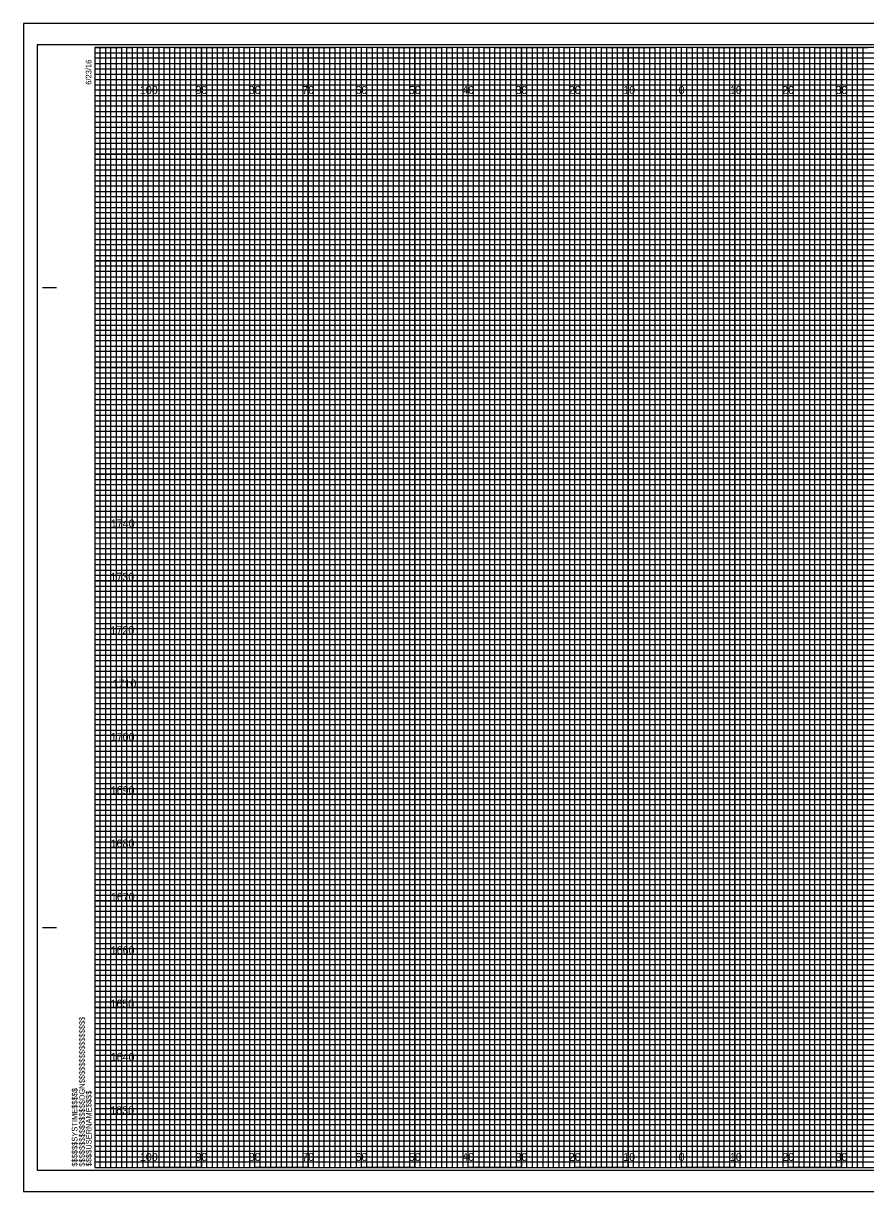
# Model space of a CAD drawing. Extents: x -13 to 323, y -5 to 6154.
# Drawn here: x -13.4 to 144.5, y 1755.5 to 1974.5 of the extents above; entities that cross this region are included whole.
import ezdxf

# ---------------------------------------------------------------- set-up
doc = ezdxf.new("R2010")
doc.units = 0
for name, color, linetype in [('Prop Retaining Wall', 7, 'Continuous'), ('Prop XS Alignment Label', 7, 'Continuous'), ('Prop XS DDE', 7, 'Continuous'), ('Prop XS DDE Elevations', 7, 'Continuous'), ('Prop XS DDE Slope Text', 7, 'Continuous'), ('Prop XS Earthwork Shape', 7, 'Continuous'), ('Prop XS Elevation Labels', 7, 'Continuous'), ('Prop XS Station Labels', 7, 'Continuous'), ('Raster_Level_0', 7, 'Continuous'), ('Scratch_Level_3', 7, 'Continuous'), ('Sheet Cutting Line CELL', 7, 'Continuous')]:
    doc.layers.add(name, color=color, linetype=linetype)

msp = doc.modelspace()

# ---------------------------------------------------------------- linework, layer by layer
at = {"layer": 'Prop Retaining Wall'}
for p, q in [((0, 1969), (260, 1969)), ((260, 1967.98), (0, 1967.98)), ((0, 1967.98), (0, 1967)), ((0, 1967), (260, 1967)), ((260, 1965.89), (0, 1965.89)), ((0, 1965.89), (0, 1964)), ((0, 1964), (320, 1964))]:
    msp.add_line(p, q, dxfattribs=at)
for points in [[(0, 1963), (270, 1963), (320, 1963), (320, 1962), (0, 1962)], [(0, 1961), (320, 1961), (320, 1959), (0, 1959)], [(0, 1958), (320, 1958), (320, 1957), (0, 1956.98)], [(0, 1956), (320, 1956), (320, 1954), (0, 1954)], [(0, 1953), (320, 1953), (320, 1952), (0, 1952)], [(0, 1951), (320, 1951), (320, 1949), (0, 1949)], [(0, 1948), (320, 1948), (320, 1947), (0, 1947)], [(0, 1946), (320, 1946), (320, 1944), (0, 1944)], [(0, 1943), (320, 1943), (320, 1942), (0, 1942)], [(0, 1941), (320, 1941), (320, 1939), (0, 1939)], [(0, 1938), (320, 1938), (320, 1937), (0, 1937)], [(0, 1936), (320, 1936), (320, 1933.95), (320, 1933), (320, 1932), (0, 1932)], [(0, 1934), (320, 1934), (320, 1933), (0, 1933)], [(0, 1931), (320, 1931), (320, 1929), (0, 1929.03)], [(0, 1929.03), (320, 1929), (320, 1928), (0, 1928)], [(0, 1927), (320, 1927), (320, 1926), (0, 1926)], [(0, 1924), (320, 1924), (320, 1923), (0, 1923)], [(0, 1922), (320, 1922), (320, 1921), (0, 1921)], [(-0.07, 1918.89), (320, 1918.89), (320, 1917.88), (-0.07, 1917.88)], [(0, 1917), (320, 1917), (320, 1916), (0, 1916)], [(0, 1914), (320, 1914), (320, 1913), (0, 1913)], [(0, 1912), (320, 1912), (320, 1911), (0, 1911)], [(0, 1909), (320, 1909), (320, 1908), (0, 1908)], [(0, 1907), (320, 1907), (320, 1906), (0, 1906)], [(0, 1904), (320, 1904), (320, 1903), (0, 1903)], [(0, 1902), (320, 1902), (320, 1901), (0, 1901)], [(0, 1899), (320, 1899), (319.99, 1897.98), (0, 1898)], [(0, 1897), (320, 1897), (320, 1896), (0, 1896)], [(0, 1894), (320, 1894), (320, 1893), (0, 1893)], [(0, 1892), (320, 1892), (320, 1891), (0, 1891)], [(0, 1889), (320, 1889), (320, 1888), (0, 1888)], [(0, 1887), (320, 1887), (320, 1886), (0, 1886)], [(0, 1884), (320, 1884), (320, 1883), (0, 1883)], [(0, 1882), (320, 1882), (320, 1881), (0, 1881)], [(0, 1879), (320, 1879), (320, 1878), (0, 1878)], [(0, 1876.99), (320.07, 1876.91), (320, 1876), (0, 1876)], [(0, 1874), (320, 1874), (320, 1873), (0, 1873)], [(0, 1872), (320, 1872), (320, 1871), (0, 1871)], [(0, 1869), (320, 1869), (320, 1868), (0, 1868)], [(0, 1867), (320, 1867), (320, 1866), (0, 1866)], [(0, 1864), (320, 1864), (320, 1863), (0, 1863)], [(0, 1862), (320, 1862), (320, 1861), (0, 1861)], [(0, 1859), (320, 1859), (320, 1858), (0, 1858)], [(0, 1857), (320, 1857), (320, 1856), (0, 1856)], [(0, 1854), (320, 1854), (320, 1853), (0, 1853)], [(0, 1852), (320, 1852), (320, 1851), (0, 1851)], [(0, 1849), (320, 1849), (320, 1848), (0, 1848)], [(0, 1847), (320, 1847), (320, 1846), (0, 1846)], [(0, 1844), (320, 1844), (320, 1843), (0, 1843)], [(0, 1842), (320, 1842), (320, 1841), (0, 1841)], [(0, 1839), (320, 1839), (319.99, 1837.98), (0, 1838)], [(0, 1837), (320, 1837), (320, 1836), (0, 1836)], [(0, 1834), (320, 1834), (320, 1833), (0, 1833)], [(0, 1832), (320, 1832), (320, 1831), (0, 1831)], [(0, 1829), (320, 1829), (320, 1828), (0, 1828)], [(0, 1827), (320, 1827), (320, 1826), (0, 1826)], [(0, 1824), (320, 1824), (320, 1823), (0, 1823)], [(0, 1822), (320, 1822), (320, 1821), (0, 1821)], [(0, 1819), (320, 1819), (320, 1818), (0, 1818)], [(0, 1816.99), (320.07, 1816.91), (320, 1816), (0, 1816)], [(0, 1814), (320, 1814), (320, 1813), (0, 1813)], [(0, 1812), (320, 1812), (320, 1811), (0, 1811)], [(0, 1809), (320, 1809), (320, 1808), (0, 1808)], [(0, 1807), (320, 1807), (320, 1806), (0, 1806)], [(0, 1804), (320, 1804), (320, 1803), (0, 1803)], [(0, 1802), (320, 1802), (320, 1801), (0, 1801)], [(0, 1799), (320, 1799), (320, 1798), (0, 1798)], [(0, 1797), (320, 1797), (320, 1796), (0, 1796)], [(0, 1794), (320, 1794), (320, 1793), (0, 1793)], [(0, 1792), (320, 1792), (320, 1791), (0, 1791)], [(0, 1789), (320, 1789), (320, 1788), (0, 1788)], [(0, 1787), (320, 1787), (320, 1786), (0, 1786)], [(0, 1784), (320, 1784), (320, 1783), (0, 1783)], [(0, 1782), (320, 1782), (320, 1781), (0, 1781)], [(0, 1779), (320, 1779), (320, 1778), (0, 1778)], [(0, 1777), (320, 1777), (320, 1776), (0, 1776)], [(0, 1774), (320, 1774), (320, 1773), (0, 1773)], [(0, 1772), (320, 1772), (320, 1771), (0, 1771)], [(0, 1769), (320, 1769), (320, 1768), (0, 1768)], [(0, 1767), (320, 1767), (320, 1766), (0, 1766)], [(0, 1764), (320, 1764), (320, 1763), (0, 1763)], [(0, 1762), (320, 1762), (320, 1761), (0, 1761)]]:
    msp.add_lwpolyline(points, dxfattribs=at)
at = {"layer": 'Prop XS Alignment Label'}
for p, q in [((-9.8, 1925), (-7.3, 1925)), ((-9.7, 1925), (-7.2, 1925)), ((-9.8, 1805), (-7.3, 1805)), ((-9.7, 1805), (-7.2, 1805)), ((0, 1760), (0, 1760)), ((0, 1760), (0, 1760)), ((0, 1760), (0, 1760)), ((0, 1760), (0, 1760)), ((0, 1760), (0, 1760)), ((0, 1760), (0, 1760)), ((0, 1760), (0, 1760))]:
    msp.add_line(p, q, dxfattribs=at)
msp.add_lwpolyline([(320, 1970), (0, 1970), (0, 1760), (320, 1760)], close=True, dxfattribs=at)
at = {"layer": 'Prop XS DDE'}
msp.add_lwpolyline([(-13.4, 1755.5), (323.3, 1755.5), (323.3, 1974.5), (-13.4, 1974.5)], close=True, dxfattribs=at)
at = {"layer": 'Prop XS DDE Elevations'}
for p, q in [((10, 1760), (10, 1970)), ((20, 1760), (20, 1970)), ((30, 1760), (30, 1970)), ((40, 1760), (40, 1970)), ((50, 1760), (50, 1970)), ((60, 1760), (60, 1970)), ((70, 1760), (70, 1970)), ((80, 1760), (80, 1970)), ((90, 1760), (90, 1970)), ((100, 1760), (100, 1970)), ((110, 1760), (110, 1970)), ((120, 1760), (120, 1970)), ((130, 1760), (130, 1970)), ((140, 1760), (140, 1970)), ((0, 1960), (320, 1960)), ((0, 1950), (320, 1950)), ((0, 1940), (320, 1940)), ((0, 1930), (320, 1930)), ((0, 1920), (320, 1920)), ((0, 1910), (320, 1910)), ((0, 1900), (320, 1900)), ((0, 1890), (320, 1890)), ((0, 1880), (320, 1880)), ((0, 1870), (320, 1870)), ((0, 1860), (320, 1860)), ((0, 1850), (320, 1850)), ((0, 1840), (320, 1840)), ((0, 1830), (320, 1830)), ((0, 1820), (320, 1820)), ((0, 1810), (320, 1810)), ((0, 1800), (320, 1800)), ((0, 1790), (320, 1790)), ((0, 1780), (320, 1780)), ((0, 1770), (320, 1770))]:
    msp.add_line(p, q, dxfattribs=at)
at = {"layer": 'Prop XS DDE Slope Text'}
msp.add_lwpolyline([(-10.8, 1759.5), (322.4, 1759.5), (322.4, 1970.5), (-10.8, 1970.5)], close=True, dxfattribs=at)
at = {"layer": 'Prop XS Earthwork Shape'}
for p, q in [((10, 1970), (0, 1970)), ((10, 1760), (10, 1970)), ((30, 1970), (20, 1970)), ((20, 1970), (20, 1760)), ((30, 1760), (30, 1970)), ((50, 1970), (40, 1970)), ((40, 1970), (40, 1760)), ((50, 1760), (50, 1970)), ((70, 1970), (60, 1970)), ((60, 1970), (60, 1760)), ((70, 1760), (70, 1970)), ((90, 1970), (80, 1970)), ((80, 1970), (80, 1760)), ((90, 1760), (90, 1970)), ((110, 1970), (100, 1970)), ((100, 1970), (100, 1760)), ((110, 1760), (110, 1970)), ((130, 1970), (120, 1970)), ((120, 1970), (120, 1760)), ((130, 1760), (130, 1970)), ((150, 1970), (140, 1970)), ((140, 1970), (140, 1760)), ((20, 1760), (10, 1760)), ((40, 1760), (30, 1760)), ((60, 1760), (50, 1760)), ((80, 1760), (70, 1760)), ((100, 1760), (90, 1760)), ((120, 1760), (110, 1760)), ((140, 1760), (130, 1760))]:
    msp.add_line(p, q, dxfattribs=at)
for points in [[(0, 1960), (320, 1960), (320, 1950), (0, 1950)], [(0, 1940), (320, 1940), (320, 1930), (0, 1930)], [(0, 1920), (320, 1920), (320, 1910), (0, 1910)], [(0, 1900), (320, 1900), (320, 1890), (0, 1890)], [(0, 1880), (320, 1880), (320, 1870), (0, 1870)], [(0, 1860), (320, 1860), (320, 1850), (0, 1850)], [(0, 1840), (320, 1840), (320, 1830), (0, 1830)], [(0, 1820), (320, 1820), (320, 1810), (0, 1810)], [(0, 1800), (320, 1800), (320, 1790), (0, 1790)], [(0, 1780), (320, 1780), (320, 1770), (0, 1770)]]:
    msp.add_lwpolyline(points, dxfattribs=at)
at = {"layer": 'Prop XS Elevation Labels'}
for points in [[(0, 1760), (1, 1760), (1, 1970), (2, 1970), (2, 1760)], [(2, 1760), (3, 1760), (3, 1970), (4, 1970), (4, 1760)], [(5, 1760), (6, 1760), (6, 1970), (7, 1970), (7, 1760)], [(7, 1760), (8, 1760), (8, 1970), (9, 1970), (9, 1760)], [(10, 1760), (11, 1760), (11, 1970), (12, 1970), (12, 1760)], [(12, 1760), (13, 1760), (13, 1970), (14, 1970), (14, 1760)], [(15, 1760), (16, 1760), (16, 1970), (17, 1970), (17, 1760)], [(17, 1760), (18, 1760), (18, 1970), (19, 1970), (19, 1760)], [(20, 1760), (21, 1760), (21, 1970), (22, 1970), (22, 1760)], [(22, 1760), (23, 1760), (23, 1970), (24, 1970), (24, 1760)], [(25, 1760), (26, 1760), (26, 1970), (27, 1970), (27, 1760)], [(27, 1760), (28, 1760), (28, 1970), (29, 1970), (29, 1760)], [(30, 1760), (31, 1760), (31, 1970), (32, 1970), (32, 1760)], [(32, 1760), (33, 1760), (33, 1970), (34, 1970), (34, 1760)], [(35, 1760), (36, 1760), (36, 1970), (37, 1970), (37, 1760)], [(37, 1760), (38, 1760), (38, 1970), (39, 1970), (39, 1760)], [(40, 1760), (41, 1760), (41, 1970), (42, 1970), (42, 1760)], [(42, 1760), (43, 1760), (43, 1970), (44, 1970), (44, 1760)], [(45, 1760), (46, 1760), (46, 1970), (47, 1970), (47, 1760)], [(47, 1760), (48, 1760), (48, 1970), (49, 1970), (49, 1760)], [(50, 1760), (51, 1760), (51, 1970), (52, 1970), (52, 1760)], [(52, 1760), (53, 1760), (53, 1970), (54, 1970), (54, 1760)], [(55, 1760), (56, 1760), (56, 1970), (57, 1970), (57, 1760)], [(57, 1760), (58, 1760), (58, 1970), (59, 1970), (59, 1760)], [(60, 1760), (61, 1760), (61, 1970), (62, 1970), (62, 1760)], [(62, 1760), (63, 1760), (63, 1970), (64, 1970), (64, 1760)], [(65, 1760), (66, 1760), (66, 1970), (67, 1970), (67, 1760)], [(67, 1760), (68, 1760), (68, 1970), (69, 1970), (69, 1760)], [(70, 1760), (71, 1760), (71, 1970), (72, 1970), (72, 1760)], [(72, 1760), (73, 1760), (73, 1970), (74, 1970), (74, 1760)], [(75, 1760), (76, 1760), (76, 1970), (77, 1970), (77, 1760)], [(77, 1760), (78, 1760), (78, 1970), (79, 1970), (79, 1760)], [(80, 1760), (81, 1760), (81, 1970), (82, 1970), (82, 1760)], [(82, 1760), (83, 1760), (83, 1970), (84, 1970), (84, 1760)], [(85, 1760), (86, 1760), (86, 1970), (87, 1970), (87, 1760)], [(87, 1760), (88, 1760), (88, 1970), (89, 1970), (89, 1760)], [(90, 1760), (91, 1760), (91, 1970), (92, 1970), (92, 1760)], [(92, 1760), (93, 1760), (93, 1970), (94, 1970), (94, 1760)], [(95, 1760), (96, 1760), (96, 1970), (97, 1970), (97, 1760)], [(97, 1760), (98, 1760), (98, 1970), (99, 1970), (99, 1760)], [(100, 1760), (101, 1760), (101, 1970), (102, 1970), (102, 1760)], [(102, 1760), (103, 1760), (103, 1970), (104, 1970), (104, 1760)], [(105, 1760), (106, 1760), (106, 1970), (107, 1970), (107, 1760)], [(107, 1760), (108, 1760), (108, 1970), (109, 1970), (109, 1760)], [(110, 1760), (111, 1760), (111, 1970), (112, 1970), (112, 1760)], [(112, 1760), (113, 1760), (113, 1970), (114, 1970), (114, 1760)], [(115, 1760), (116, 1760), (116, 1970), (117, 1970), (117, 1760)], [(117, 1760), (118, 1760), (118, 1970), (119, 1970), (119, 1760)], [(120, 1760), (121, 1760), (121, 1970), (122, 1970), (122, 1760)], [(122, 1760), (123, 1760), (123, 1970), (124, 1970), (124, 1760)], [(125, 1760), (126, 1760), (126, 1970), (127, 1970), (127, 1760)], [(127, 1760), (128, 1760), (128, 1970), (129, 1970), (129, 1760)], [(130, 1760), (131, 1760), (131, 1970), (132, 1970), (132, 1760)], [(132, 1760), (133, 1760), (133, 1970), (134, 1970), (134, 1760)], [(135, 1760), (136, 1760), (136, 1970), (137, 1970), (137, 1760)], [(137, 1760), (138, 1760), (138, 1970), (139, 1970), (139, 1760)], [(140, 1760), (141, 1760), (141, 1970), (142, 1970), (142, 1760)], [(142, 1760), (143, 1760), (143, 1970), (144, 1970), (144, 1760)]]:
    msp.add_lwpolyline(points, dxfattribs=at)
at = {"layer": 'Prop XS Station Labels'}
for points in [[(0, 1970), (5, 1970), (5, 1760), (15, 1760), (15, 1970), (25, 1970), (25, 1760), (35, 1760), (35, 1970), (45, 1970), (45, 1760), (55, 1760), (55, 1970), (65, 1970), (65, 1760), (75, 1760), (75, 1970), (85, 1970), (85, 1760), (95, 1760), (95, 1970), (105, 1970), (105, 1760), (115, 1760), (115, 1970), (125, 1970), (125, 1760), (135, 1760), (135, 1970), (145, 1970)], [(0, 1965), (275, 1965)], [(0, 1945), (320, 1945), (320, 1955), (0, 1955)], [(0, 1925), (320, 1925), (320, 1935), (0, 1935)], [(0, 1905), (320, 1905), (320, 1915), (0, 1915)], [(0, 1885), (320, 1885), (320, 1895), (0, 1895)], [(0, 1865), (320, 1865), (320, 1875), (0, 1875)], [(0, 1845), (320, 1845), (320, 1855), (0, 1855)], [(0, 1825), (320, 1825), (320, 1835), (0, 1835)], [(0, 1805), (320, 1805), (320, 1815), (0, 1815)], [(0, 1785), (320, 1785), (320, 1795), (0, 1795)], [(0, 1765), (320, 1765), (320, 1775), (0, 1775)]]:
    msp.add_lwpolyline(points, dxfattribs=at)
at = {"layer": 'Sheet Cutting Line CELL'}
for p, q in [((323.3, 1974.5), (-13.4, 1974.5)), ((-13.4, 1974.5), (-13.4, 1755.5)), ((-13.4, 1755.5), (323.3, 1755.5))]:
    msp.add_line(p, q, dxfattribs=at)

# ---------------------------------------------------------------- texts
at = {"layer": 'Prop XS Alignment Label'}
for s, p in [('6/23/16', (-0.65, 1963)), ('$$$$$$$$$$$$$$$$DGN$$$$$$$$$$$$$$$$', (-1.88, 1760.18)), ('$$$$$$SYSTIME$$$$$', (-3.26, 1760.18)), ('$$$$USERNAME$$$$', (-0.62, 1760.23))]:
    msp.add_text(s, height=1.05, rotation=90, dxfattribs=at).set_placement(p)
at = {"layer": 'Raster_Level_0'}
for s, p in [('100', (8.44, 1961.25)), ('90', (18.86, 1961.25)), ('80', (28.86, 1961.25)), ('70', (38.86, 1961.25)), ('60', (48.86, 1961.25)), ('50', (58.86, 1961.25)), ('40', (68.86, 1961.25)), ('30', (78.86, 1961.25)), ('20', (88.86, 1961.25)), ('10', (99.04, 1961.25)), ('0', (109.45, 1961.25)), ('0', (109.45, 1961.25)), ('10', (119.04, 1961.25)), ('20', (128.86, 1961.25)), ('30', (138.86, 1961.25)), ('100', (8.44, 1761.25)), ('90', (18.86, 1761.25)), ('80', (28.86, 1761.25)), ('70', (38.86, 1761.25)), ('60', (48.86, 1761.25)), ('50', (58.86, 1761.25)), ('40', (68.86, 1761.25)), ('30', (78.86, 1761.25)), ('20', (88.86, 1761.25)), ('10', (99.04, 1761.25)), ('0', (109.45, 1761.25)), ('0', (109.45, 1761.25)), ('10', (119.04, 1761.25)), ('20', (128.86, 1761.25)), ('30', (138.86, 1761.25))]:
    msp.add_text(s, height=1.5, dxfattribs=at).set_placement(p)
at = {"layer": 'Scratch_Level_3'}
for s, p in [('1740', (3, 1880)), ('1730', (2.92, 1870)), ('1720', (2.93, 1860)), ('1710', (3.31, 1850)), ('1700', (2.98, 1840)), ('1690', (2.97, 1830)), ('1680', (2.95, 1820)), ('1670', (3, 1810)), ('1660', (2.97, 1800)), ('1650', (2.92, 1790)), ('1640', (2.97, 1780)), ('1630', (2.89, 1770))]:
    msp.add_text(s, height=1.5, dxfattribs=at).set_placement(p)

doc.saveas('drawing.dxf')
